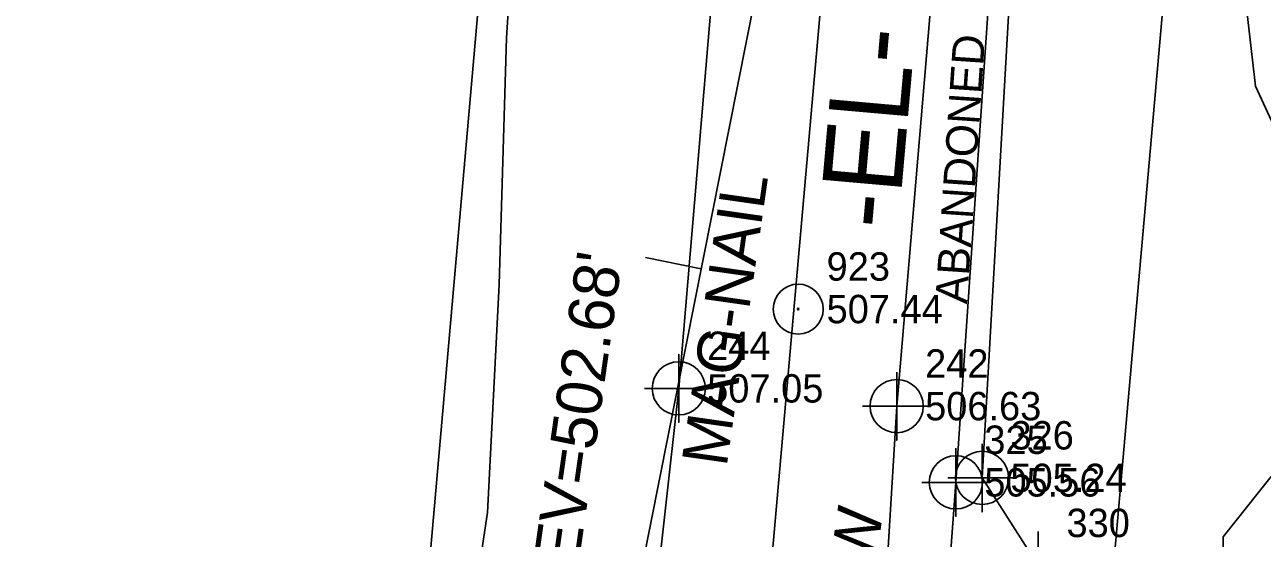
# Model space of a CAD drawing. Extents: x 1698744 to 1699848, y 707609 to 709748.
# Drawn here: x 1699347.3 to 1699456.2, y 708851.5 to 708896.7 of the extents above; entities that cross this region are included whole.
import ezdxf

# ---------------------------------------------------------------- set-up
doc = ezdxf.new("R2010")
doc.units = 0
for name, color, linetype in [('Exist Horizontal Alignment', 7, 'Continuous'), ('Exist Horizontal Alignment Direction Label', 7, 'Continuous'), ('Exist Horizontal Baseline Alignment', 7, 'Continuous'), ('Exist Horizontal Baseline Alignment Tick small', 7, 'Continuous'), ('Exist Property Iron Pin Text', 7, 'Continuous'), ('Exist Right of Way Line', 7, 'Continuous'), ('Exist Structure Major Bridge Seat Top Elevation', 7, 'Continuous'), ('Exist Structure Major Bridge WW Text', 7, 'Continuous'), ('Exist Utilities Telephone UG Cable', 7, 'Continuous'), ('Exist Utilities Telephone UG Cable Text', 7, 'Continuous'), ('Exist Vegetation Woods Line', 7, 'Continuous'), ('Prop Conc Shoulder Berm Gutter', 7, 'Continuous'), ('Prop Horizontal Alignment Station Label', 7, 'Continuous'), ('Prop North Arrow NAD83 for Plan Sheets CELL', 7, 'Continuous'), ('Prop Roadway Bridge', 7, 'Continuous'), ('Prop Superelevation  Arrow CELL', 7, 'Continuous'), ('Prop Superelevation Label', 7, 'Continuous'), ('Sheet Border Standard 30in CELL', 7, 'Continuous'), ('Sheet Data Field CELL', 7, 'Continuous'), ('Sheet Plot Border Inside CELL', 7, 'Continuous'), ('Sheet Sticker Preliminary CELL', 7, 'Continuous')]:
    doc.layers.add(name, color=color, linetype=linetype)

msp = doc.modelspace()

# ---------------------------------------------------------------- linework, layer by layer
at = {"layer": 'Exist Horizontal Alignment'}
msp.add_line((1699410.42, 708819.67), (1699421.65, 708947.03), dxfattribs=at)
at = {"layer": 'Exist Horizontal Baseline Alignment'}
msp.add_line((1699395.77, 708819.44), (1699513.15, 709411.06), dxfattribs=at)
at = {"layer": 'Exist Horizontal Baseline Alignment Tick small'}
msp.add_line((1699406.84, 708875.24), (1699401.93, 708876.22), dxfattribs=at)
at = {"layer": 'Exist Right of Way Line'}
for p, q in [((1699380.54, 708822.3), (1699391.76, 708949.66)), ((1699440.3, 708817.03), (1699451.53, 708944.39))]:
    msp.add_line(p, q, dxfattribs=at)
at = {"layer": 'Exist Utilities Telephone UG Cable'}
for points in [[(1699441.75, 708843.06), (1699433.58, 708844.03), (1699428.5, 708846.07), (1699429.26, 708856.44), (1699434.77, 708937.33), (1699437.75, 708973.12), (1699443.66, 709022.32), (1699451.83, 709072.31), (1699454.23, 709094.33), (1699457.14, 709107.37), (1699468.04, 709152.27), (1699491.2, 709236.57), (1699501.58, 709271.54), (1699517.86, 709327.49), (1699534.26, 709386.49)], [(1699441.69, 708843.63), (1699436.49, 708849.12), (1699431.56, 708856.83), (1699436.15, 708937.18), (1699439.02, 708973.24), (1699445.51, 709022.28), (1699452.85, 709072.16), (1699456.95, 709089.86), (1699470.27, 709085.91), (1699457.57, 709091.24), (1699461.33, 709106.86), (1699471.7, 709151.67), (1699493.37, 709235.72), (1699503.07, 709271.03), (1699519.14, 709327.08), (1699535.26, 709386.02)]]:
    msp.add_lwpolyline(points, dxfattribs=at)
at = {"layer": 'Exist Vegetation Woods Line'}
for points in [[(1699391.24, 708919.37), (1699389.71, 708895.57), (1699389.06, 708873.84), (1699388.04, 708853.8), (1699385.67, 708837.97), (1699382.24, 708825.72), (1699378.47, 708814.47), (1699377.22, 708804.59), (1699378.09, 708794.52), (1699378.73, 708783.48), (1699377.79, 708772.88), (1699375.75, 708768.17), (1699370.11, 708769.87), (1699364.89, 708776.22), (1699357.47, 708784.9), (1699347.08, 708793.81), (1699337.26, 708798.02), (1699327.17, 708796.93), (1699316.79, 708795.32), (1699302.38, 708798), (1699289.18, 708801.44), (1699277.16, 708805.39)], [(1699460.74, 708880.24), (1699455.62, 708891.31), (1699454.18, 708903.84)], [(1699459.44, 708763.77), (1699451.04, 708766.64), (1699444.67, 708767.48), (1699439.46, 708769.71), (1699435.8, 708776.34), (1699436.7, 708783.71), (1699437.77, 708793.91), (1699440.55, 708804.9), (1699444.75, 708816.53), (1699449.9, 708830.76), (1699451.19, 708834.34), (1699452.71, 708842.71), (1699452.77, 708851.63), (1699457.01, 708856.95)]]:
    msp.add_lwpolyline(points, dxfattribs=at)
at = {"layer": 'Prop Horizontal Alignment Station Label'}
for radius in [2.2, 0.0707]:
    msp.add_circle((1699415.38, 708871.69), radius, dxfattribs=at)
at = {"layer": 'Prop North Arrow NAD83 for Plan Sheets CELL'}
for points in [[(1699431.56, 708859.83), (1699431.56, 708853.83), (1699431.56, 708856.83), (1699434.56, 708856.83), (1699428.56, 708856.83)], [(1699429.26, 708859.44), (1699429.26, 708853.44), (1699429.26, 708856.44), (1699432.26, 708856.44), (1699426.26, 708856.44)], [(1699436.49, 708852.12), (1699436.49, 708846.12), (1699436.49, 708849.12), (1699439.49, 708849.12), (1699433.49, 708849.12)]]:
    msp.add_lwpolyline(points, dxfattribs=at)
for centre in [(1699429.26, 708856.44), (1699431.56, 708856.83)]:
    msp.add_circle(centre, 2.34, dxfattribs=at)
at = {"layer": 'Sheet Border Standard 30in CELL'}
for points in [[(1699404.87, 708867.71), (1699404.87, 708861.71), (1699404.87, 708864.71), (1699407.87, 708864.71), (1699401.87, 708864.71)], [(1699424.05, 708866.15), (1699424.05, 708860.15), (1699424.05, 708863.15), (1699427.05, 708863.15), (1699421.05, 708863.15)]]:
    msp.add_lwpolyline(points, dxfattribs=at)
for centre in [(1699404.87, 708864.71), (1699424.05, 708863.15)]:
    msp.add_circle(centre, 2.34, dxfattribs=at)
at = {"layer": 'Sheet Sticker Preliminary CELL'}
for points in [[(1699523.53, 709430.62), (1699509.87, 709380.4), (1699496.34, 709331.75), (1699485.4, 709292.12), (1699472.33, 709243.96), (1699460.09, 709200.29), (1699447.67, 709153.3), (1699439.13, 709119.78), (1699431.13, 709081.41), (1699425.58, 709052.98), (1699419.28, 709011.91), (1699415.32, 708978.51), (1699411.44, 708941.68), (1699408.45, 708907.15), (1699404.87, 708864.71), (1699401.1, 708830.74), (1699396.87, 708803.49)], [(1699542.38, 709424.6), (1699528.69, 709374.56), (1699515.83, 709327.15), (1699504.48, 709285.96), (1699491.02, 709238.81), (1699478.11, 709193.7), (1699466.3, 709148.31), (1699457.9, 709114.22), (1699449.99, 709078.09), (1699444.65, 709048.51), (1699438.62, 709008.95), (1699434.24, 708974.87), (1699430.76, 708939.89), (1699427.59, 708904.74), (1699424.05, 708863.15), (1699421.85, 708827.25), (1699420.58, 708799.94)]]:
    msp.add_lwpolyline(points, dxfattribs=at)

# ---------------------------------------------------------------- texts
at = {"layer": 'Exist Horizontal Alignment Direction Label'}
msp.add_text('-EL-', height=7, rotation=84.9628, dxfattribs=at).set_placement((1699424.16, 708878.58))
at = {"layer": 'Exist Property Iron Pin Text'}
msp.add_text('MAG-NAIL', height=4, rotation=81.8738, dxfattribs=at).set_placement((1699409.08, 708857.73))
at = {"layer": 'Exist Structure Major Bridge Seat Top Elevation'}
msp.add_text("SEAT ELEV=502.68'", height=4, rotation=81.8738, dxfattribs=at).set_placement((1699392.92, 708827.23))
at = {"layer": 'Exist Structure Major Bridge WW Text'}
msp.add_text('WOOD END & WW', height=4, rotation=81.8738, dxfattribs=at).set_placement((1699416.28, 708807.76))
at = {"layer": 'Exist Utilities Telephone UG Cable Text'}
msp.add_text('ABANDONED', height=2.8, rotation=86.102, dxfattribs=at).set_placement((1699430.23, 708872.1))
at = {"layer": 'Prop Conc Shoulder Berm Gutter'}
msp.add_text('507.44', height=2.5, dxfattribs=at).set_placement((1699417.88, 708870.44))
at = {"layer": 'Prop Roadway Bridge'}
for s, p in [('505.56', (1699431.76, 708855.19)), ('505.24', (1699434.06, 708855.58))]:
    msp.add_text(s, height=2.5, dxfattribs=at).set_placement(p)
at = {"layer": 'Prop Superelevation  Arrow CELL'}
msp.add_text('923', height=2.5, dxfattribs=at).set_placement((1699417.88, 708874.19))
at = {"layer": 'Prop Superelevation Label'}
for s, p in [('325', (1699431.76, 708858.94)), ('326', (1699434.06, 708859.33)), ('330', (1699438.99, 708851.62))]:
    msp.add_text(s, height=2.5, dxfattribs=at).set_placement(p)
at = {"layer": 'Sheet Data Field CELL'}
for s, p in [('244', (1699407.37, 708867.21)), ('242', (1699426.55, 708865.65))]:
    msp.add_text(s, height=2.5, dxfattribs=at).set_placement(p)
at = {"layer": 'Sheet Plot Border Inside CELL'}
for s, p in [('507.05', (1699407.37, 708863.46)), ('506.63', (1699426.55, 708861.9))]:
    msp.add_text(s, height=2.5, dxfattribs=at).set_placement(p)

doc.saveas('drawing.dxf')
